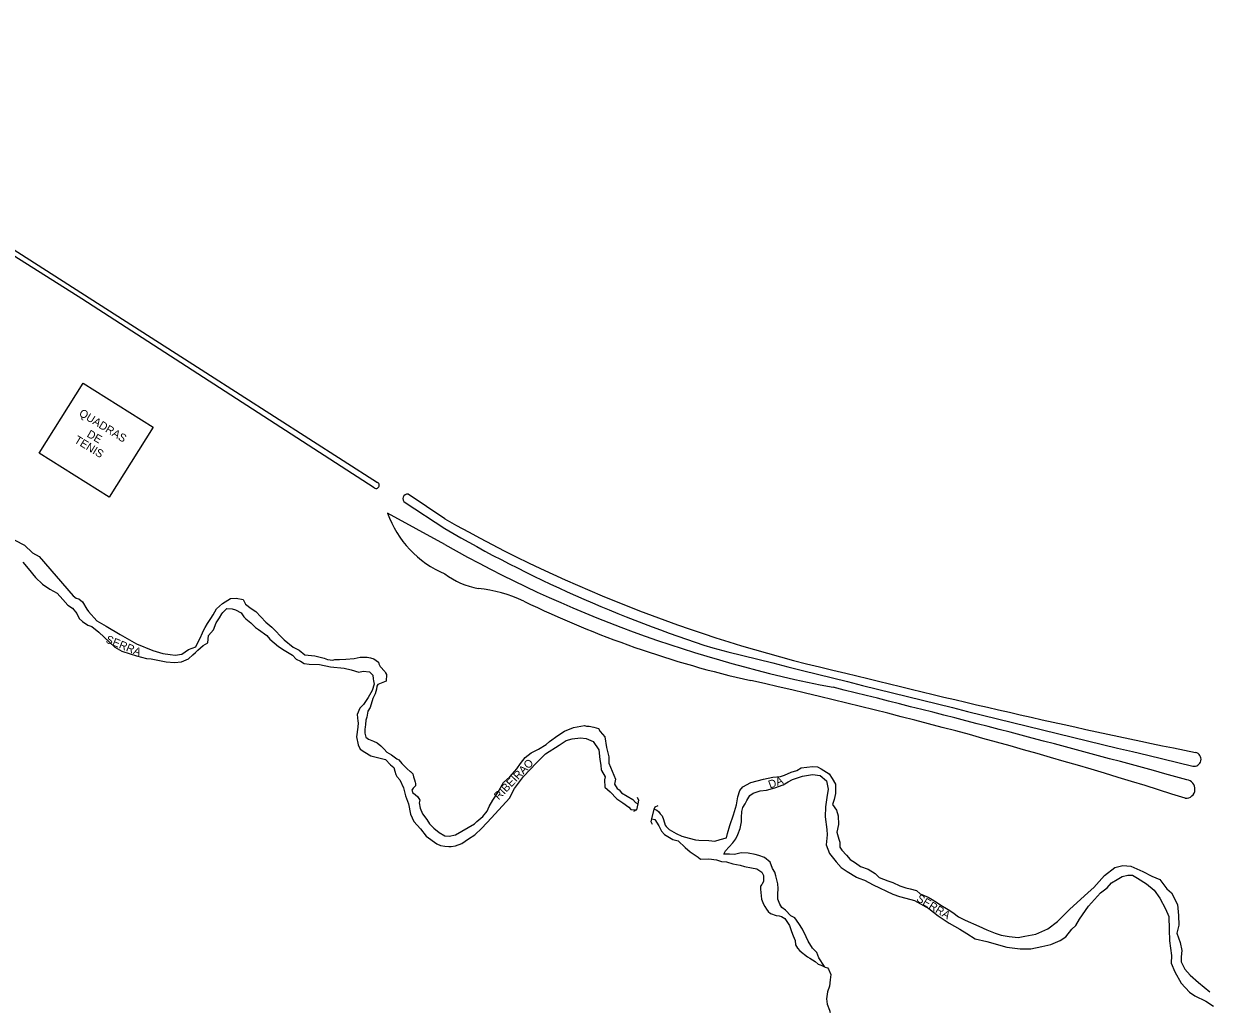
# Model space of a CAD drawing. Extents: x 325899 to 363134, y 7578590 to 7592502.
# Drawn here: x 342271 to 342864, y 7589009 to 7589502 of the extents above; entities that cross this region are included whole.
import ezdxf

# ---------------------------------------------------------------- set-up
doc = ezdxf.new("R2010")
doc.units = 0
for name, color, linetype in [('EDIFEXISTENT', 7, 'Continuous'), ('EDIFIDENTIF', 7, 'Continuous'), ('EDIFOBRAEXIS', 7, 'Continuous')]:
    doc.layers.add(name, color=color, linetype=linetype)

msp = doc.modelspace()

# ---------------------------------------------------------------- linework, layer by layer
at = {"layer": 'EDIFEXISTENT'}
for p, q in [((342278.67, 7589287.14), (342300.64, 7589322.17)), ((342300.64, 7589322.17), (342335.54, 7589300.21)), ((342335.54, 7589300.21), (342313.52, 7589265.21)), ((342313.52, 7589265.21), (342278.67, 7589287.14)), ((342577.86, 7589111.85), (342577.22, 7589108.75)), ((342577.62, 7589115.2), (342578.27, 7589113.6)), ((342578.27, 7589113.6), (342577.86, 7589111.85)), ((342577.22, 7589108.75), (342575.67, 7589107.99)), ((342584.87, 7589104.29), (342586.08, 7589109.06)), ((342586.08, 7589109.06), (342586.54, 7589110.38)), ((342586.54, 7589110.38), (342588.1, 7589110.93)), ((342584.62, 7589102.82), (342584.87, 7589104.29)), ((342585.18, 7589101.48), (342584.62, 7589102.82))]:
    msp.add_line(p, q, dxfattribs=at)
at = {"layer": 'EDIFOBRAEXIS'}
for points in [[(342446.11, 7589269.87), (342299.94, 7589364.31), (342199.85, 7589427.54), (342086.62, 7589501.91)], [(342092.03, 7589501.91), (342154.85, 7589460.08), (342361.94, 7589327.42), (342447.7, 7589272.56)], [(342481.39, 7589254.31), (342463, 7589266.71)], [(342461.57, 7589262.53), (342481.39, 7589249.43)], [(342481.39, 7589241.4), (342452.76, 7589257.13)], [(342266.44, 7589243.62), (342271.3, 7589241.16), (342275.33, 7589237.27), (342278.58, 7589235.4), (342295.64, 7589215.8), (342297.13, 7589214.57), (342298.43, 7589214.33), (342300.31, 7589212.88), (342302.43, 7589209.22), (342303.26, 7589207.91), (342307.49, 7589203.36), (342312.02, 7589200.61), (342319.06, 7589196.55), (342327.22, 7589191.77), (342335.39, 7589188.54), (342340.47, 7589186.94), (342344.01, 7589186.48), (342346.61, 7589186.18), (342349.86, 7589186.65), (342353.21, 7589188.97), (342356.91, 7589190.24), (342358.17, 7589192.82), (342359.06, 7589194.69), (342360.2, 7589197.24), (342360.95, 7589198.75), (342361.57, 7589199.98), (342362.71, 7589202.03), (342364.34, 7589204.41), (342365.59, 7589206.36), (342367.23, 7589209.27), (342370.2, 7589211.95), (342374.29, 7589214.47), (342377.13, 7589214.58), (342380.6, 7589214.01), (342381.77, 7589211.61), (342384.64, 7589209.43), (342386.92, 7589207.96), (342391.84, 7589202.7), (342394.92, 7589200.19), (342401.07, 7589193.89), (342405.64, 7589190.1), (342408.63, 7589188.69), (342411.5, 7589186.38), (342416.49, 7589185.83), (342421.16, 7589184.69), (342422.72, 7589183.92), (342425.34, 7589183.62), (342426.43, 7589183.97), (342428.79, 7589184), (342431.89, 7589184.08), (342436.03, 7589184.44), (342439.12, 7589185.19), (342442.53, 7589185.2), (342444.21, 7589184.74), (342445.95, 7589184.3), (342448.18, 7589182.6), (342448.37, 7589181.76), (342449.07, 7589180.5), (342451.46, 7589177.96), (342451.8, 7589177.33), (342452.19, 7589176.49), (342452.05, 7589173.21), (342450.38, 7589172.43), (342447.88, 7589171.46), (342447.36, 7589170.59), (342447.32, 7589169.14), (342446.64, 7589166.77), (342445.34, 7589164.46), (342444.13, 7589160), (342442.95, 7589158.13), (342442.38, 7589155.1), (342441.86, 7589153.72), (342441.71, 7589151.48), (342441.6, 7589150.19), (342441.43, 7589149.12), (342441.45, 7589147.18), (342441.91, 7589145.21), (342443.32, 7589144.18), (342445.77, 7589143.17), (342447.64, 7589142.27), (342449.44, 7589140.87), (342451.08, 7589139.11), (342452.35, 7589137.6), (342454.78, 7589136.33), (342457.34, 7589134.38), (342458.47, 7589133.81), (342459.99, 7589131.97), (342461.4, 7589130.51), (342462.66, 7589129.28), (342464, 7589128), (342464.28, 7589127.93), (342464.61, 7589127.68), (342465.41, 7589126.77), (342465.76, 7589125.36), (342466.29, 7589123.86), (342466.61, 7589122.62), (342466.69, 7589121.96), (342466.78, 7589120.84), (342466.23, 7589120.25), (342465.58, 7589119.56), (342464.93, 7589118.56), (342465.42, 7589117.24), (342466.6, 7589116.44), (342467.84, 7589115.26), (342468.87, 7589113.65), (342468.51, 7589112.37), (342469.05, 7589109.61), (342470.28, 7589106.75), (342472.37, 7589104.03), (342473.82, 7589101.83), (342475.85, 7589099.64), (342478.6, 7589097.42), (342481.39, 7589095.78)], [(342270.41, 7589232.63), (342273.04, 7589229.54), (342276.72, 7589225.01), (342280.25, 7589221.57), (342284.01, 7589219.2), (342287.57, 7589217.15), (342290.48, 7589214.04), (342292.98, 7589211.22), (342295.31, 7589209.72), (342297.4, 7589207), (342298.52, 7589204.52), (342300.32, 7589202.94), (342302.89, 7589201.09), (342304.95, 7589200.48), (342308.39, 7589197.57), (342316.41, 7589190.17), (342319.89, 7589188.1), (342324.05, 7589186.8), (342327.32, 7589185.77), (342332.21, 7589184.43), (342334.66, 7589184.23), (342337.03, 7589183.8), (342342.12, 7589182.77), (342346.19, 7589182.41), (342349.83, 7589182.76), (342353.19, 7589184.35), (342355.4, 7589186.23), (342356.78, 7589187.54), (342357.84, 7589188.65), (342360.63, 7589190.94), (342362.85, 7589192.32), (342363.32, 7589195.98), (342365.75, 7589198.73), (342367.16, 7589202.26), (342368.71, 7589204.74), (342369.9, 7589206.86), (342370.5, 7589207.51), (342372.46, 7589209.44), (342375.08, 7589209.37), (342376.69, 7589208.75), (342379.56, 7589207.28), (342381, 7589205.32), (342381.85, 7589204.39), (342384.47, 7589202.26), (342386.71, 7589200), (342388.2, 7589199.02), (342392.38, 7589195.95), (342393.92, 7589194.08), (342398.21, 7589190.55), (342401.13, 7589188.68), (342405.18, 7589186.08), (342407.06, 7589184.2), (342409.3, 7589183.16), (342411.05, 7589181.93), (342413.59, 7589181.6), (342418.73, 7589181.51), (342424.31, 7589180.31), (342431.06, 7589179.6), (342434.65, 7589178.75), (342438.4, 7589177.65), (342440.61, 7589178.16), (342443.79, 7589177.74), (342445.48, 7589176.16), (342445.61, 7589174.25), (342445.77, 7589173.29), (342446.1, 7589171.69), (342445.14, 7589168.5), (342443.07, 7589165.05), (342440.8, 7589161.39), (342438.87, 7589159.63), (342437.58, 7589156.52), (342437.95, 7589153.12), (342438.06, 7589152.33), (342437.91, 7589150.22), (342437.28, 7589145.23), (342438.14, 7589141.32), (342439.16, 7589139.15), (342441.47, 7589137.57), (342444.41, 7589135.73), (342451.83, 7589133.96), (342454.25, 7589131.24), (342455.84, 7589129.94), (342456.42, 7589128.14), (342456.93, 7589126.55), (342457.4, 7589125.54), (342458.97, 7589123.85), (342460.69, 7589119.8), (342461.7, 7589115.8), (342463.18, 7589111.75), (342464.23, 7589106.6), (342465.87, 7589103.04), (342469.22, 7589099.37), (342472, 7589095.56), (342477.37, 7589091.78), (342479.23, 7589090.9), (342481.39, 7589090.7)], [(342481.39, 7589095.78), (342483.65, 7589095.68), (342486.82, 7589096.24), (342496.18, 7589101.86), (342497.44, 7589103.01), (342500.4, 7589105.41), (342502.57, 7589108.2), (342503.61, 7589110.48), (342505.39, 7589113.65), (342507.99, 7589117.48), (342510.74, 7589122.47), (342513.95, 7589125.38), (342517.41, 7589129.23), (342519.29, 7589131.92), (342521.63, 7589134.94), (342524.61, 7589137.32), (342528.17, 7589139.14), (342532.05, 7589141.49), (342533.66, 7589142.96), (342537.83, 7589145.95), (342541.23, 7589148.2), (342545.73, 7589149.97), (342551.16, 7589150.94), (342552.23, 7589150.59), (342553.62, 7589150.61), (342555.93, 7589150.12), (342558.17, 7589149.51), (342559, 7589147.96), (342561.41, 7589145.31), (342562.28, 7589139.93), (342563.34, 7589135.31), (342563.49, 7589132.21), (342566.69, 7589124.06), (342566.16, 7589121.62), (342567.57, 7589119.46), (342568.56, 7589118.72), (342569.78, 7589117.25), (342575.33, 7589113.94), (342576.72, 7589112.54), (342577.86, 7589111.85)], [(342481.39, 7589090.7), (342483.4, 7589090.54), (342484.57, 7589090.45), (342486.73, 7589090.76), (342489.99, 7589092), (342493.22, 7589094.3), (342496.35, 7589096.38), (342499.98, 7589099.62), (342504.82, 7589104.76), (342513.67, 7589114.65), (342516.3, 7589119.51), (342520.8, 7589125.44), (342527.24, 7589132.34), (342531.79, 7589136.72), (342538.63, 7589141.22), (342542.11, 7589143.4), (342545.01, 7589144.28), (342549.17, 7589144.83), (342552.14, 7589144.47), (342555.51, 7589142.94), (342558.37, 7589138.72), (342558.92, 7589133.92), (342559.42, 7589131.15), (342559.6, 7589128.84), (342559.77, 7589128.54), (342561.54, 7589125.34), (342561.26, 7589123.76), (342561.41, 7589120.11), (342564.14, 7589117.77), (342567.46, 7589114.36), (342570.45, 7589112.22), (342573.44, 7589110.11), (342574.46, 7589109.01), (342577.22, 7589108.75)], [(342586.08, 7589109.06), (342587.07, 7589108.81), (342587.43, 7589108.61), (342588.21, 7589107.92), (342589.05, 7589106.8), (342590.04, 7589105.76), (342590.82, 7589104.03), (342591.5, 7589101.16), (342592, 7589100.5), (342593.63, 7589098.97), (342597.1, 7589096.96), (342599.97, 7589095.58), (342603.59, 7589094.64), (342606.69, 7589093.79), (342608.41, 7589093.59), (342613.36, 7589093.5), (342616.38, 7589093.19), (342619.08, 7589093.97), (342622.23, 7589094.85), (342622.69, 7589097.01), (342623.84, 7589100.94), (342625.8, 7589106.29), (342627.29, 7589111.34), (342627.9, 7589115.22), (342628.92, 7589118.39), (342630.32, 7589120.3), (342634.34, 7589122.47), (342640.72, 7589124.21), (342645.41, 7589125.11), (342649.3, 7589125.54), (342651.3, 7589126.12), (342654.53, 7589127.56), (342657.33, 7589128.54), (342659.51, 7589129.81), (342665.15, 7589130.4), (342667.66, 7589130.32), (342669.59, 7589129.23), (342673.54, 7589126.73), (342675.04, 7589124.54), (342676.68, 7589121.62), (342676.67, 7589116.93), (342676.13, 7589113.91), (342675.29, 7589111.5), (342677.21, 7589108.65), (342678.04, 7589105.88), (342678.19, 7589101.41), (342677.39, 7589097.66), (342678.32, 7589094.15), (342678.96, 7589092.6), (342678.82, 7589090.07), (342679.94, 7589088.57), (342682.19, 7589086.1), (342684.14, 7589084.04), (342686.65, 7589082.33), (342689.29, 7589080.4), (342693.02, 7589079.12), (342696.54, 7589076.93), (342698.57, 7589074.97), (342702.93, 7589073.36), (342705.42, 7589072.5), (342708.91, 7589070.79), (342711.91, 7589069.79), (342714.14, 7589069.3), (342717.26, 7589068.38), (342719.14, 7589066.86), (342723.04, 7589065.12), (342725.12, 7589064.03), (342727.25, 7589062.7), (342729.38, 7589061.05), (342733.06, 7589059.04), (342735.34, 7589057.41), (342738.23, 7589055.24), (342741.52, 7589053.69), (342748.45, 7589050.63), (342752.43, 7589048.79), (342756.56, 7589047.18), (342759.58, 7589046.19), (342763.62, 7589045.39), (342767.98, 7589045.03), (342771.41, 7589045.68), (342776.97, 7589046.69), (342782.92, 7589049.24), (342787.7, 7589052.91), (342793.8, 7589059.01), (342803.03, 7589067.42), (342805.91, 7589069.98), (342811.2, 7589075.88), (342816.44, 7589079.91), (342820.4, 7589081.02), (342824.33, 7589080.65), (342830.44, 7589078.03), (342834.83, 7589075.68), (342838.89, 7589073.9), (342842.41, 7589069.32), (342844.69, 7589067.31), (342847.77, 7589061.42), (342848.14, 7589055.98), (342848.36, 7589051.16), (342847.46, 7589047.12), (342849, 7589042.48), (342849.81, 7589038.54), (342849.52, 7589035.21), (342849.49, 7589032.78), (342851.31, 7589029.2), (342854.02, 7589026.14), (342858.23, 7589022.4), (342863.96, 7589017.82)], [(342671.27, 7589030.38), (342668.45, 7589034.85), (342667.37, 7589037.52), (342665.27, 7589039.7), (342663.04, 7589043.19), (342662.13, 7589045.27), (342660.26, 7589049.11), (342658.41, 7589051.88), (342656.46, 7589054.8), (342654.38, 7589055.8), (342651.78, 7589058.62), (342649.98, 7589059.92), (342648.94, 7589061.62), (342647.93, 7589064.13), (342647.83, 7589066.57), (342648.04, 7589069.49), (342647.84, 7589071.8), (342647.26, 7589074.42), (342646.84, 7589075.86), (342646.33, 7589077.69), (342645.24, 7589079.47), (342644.06, 7589082.62), (342641.19, 7589084.94), (342638.38, 7589085.91), (342636.53, 7589086.5), (342633.13, 7589087.09), (342629.5, 7589087.32), (342626.24, 7589086.49), (342623.68, 7589086.62), (342620.97, 7589086.6), (342621.7, 7589088.28), (342623.61, 7589090.25), (342625.39, 7589092.36), (342626.87, 7589094.36), (342627.86, 7589096.46), (342629.06, 7589099.41), (342629.73, 7589102.86), (342629.71, 7589104.99), (342629.82, 7589107.93), (342630.33, 7589109.91), (342631.6, 7589111.79), (342632.44, 7589113.51), (342633.92, 7589116), (342635.52, 7589117.06), (342639.15, 7589118.27), (342642.2, 7589118.7), (342646.34, 7589119.88), (342650.53, 7589121.3), (342653.13, 7589122.79), (342655.29, 7589123.95), (342660.21, 7589125.64), (342665.19, 7589126.49), (342669, 7589126.05), (342672.22, 7589123.31), (342673.12, 7589119.19), (342672.38, 7589114.9), (342671.66, 7589110.29), (342671.59, 7589105.23), (342672.47, 7589099.01), (342672.54, 7589096.27), (342672.12, 7589091.27), (342673.74, 7589086.93), (342677.11, 7589082.76), (342679.64, 7589079.91), (342682.58, 7589077.92), (342687.3, 7589075.1), (342688.39, 7589074.61), (342691.28, 7589073.59), (342695.49, 7589071.22), (342705.45, 7589066.61), (342708.75, 7589065.38), (342711.95, 7589064.71), (342716.24, 7589063.46), (342723.36, 7589059.44), (342728.07, 7589055.82), (342733.52, 7589052.1), (342738.9, 7589049.15), (342742.37, 7589046.98), (342746.58, 7589044.23), (342752.32, 7589042.9), (342762.41, 7589040.11), (342769.09, 7589039.37), (342774.44, 7589039.33), (342779.85, 7589040.54), (342784.4, 7589041.52), (342789, 7589043.49), (342791.89, 7589045.23), (342794.87, 7589049.11), (342796.96, 7589051.01), (342798.69, 7589054.18), (342803.22, 7589060.69), (342809.18, 7589067.33), (342812.53, 7589069.76), (342814.75, 7589072.25), (342817.49, 7589073.97), (342820.08, 7589075.41), (342822.95, 7589076.14), (342825.24, 7589076.11), (342827.77, 7589074.61), (342832.23, 7589071.75), (342836.11, 7589068.6), (342838.95, 7589064.58), (342841.75, 7589059.27), (342843.34, 7589055.41), (342843.48, 7589049.01), (342843.78, 7589043.35), (342844.73, 7589035.91), (342844.49, 7589032.13), (342846.43, 7589027.71), (342849.6, 7589022.12), (342853.65, 7589017.69), (342856.36, 7589015.73), (342861.89, 7589013.16), (342865.8, 7589010.64)], [(342584.87, 7589104.29), (342586.33, 7589103.91), (342588.4, 7589100.78), (342589.74, 7589098.17), (342591.18, 7589096.41), (342595.37, 7589093.99), (342598.03, 7589093.33), (342601.65, 7589089.94), (342604.11, 7589087.76), (342608.09, 7589085.06), (342609.31, 7589084.09), (342613.35, 7589084.28), (342617.23, 7589083.72), (342619.66, 7589082.88), (342622.23, 7589082.72), (342625.47, 7589081.8), (342629.05, 7589081.21), (342631.16, 7589080.42), (342634.66, 7589079.82), (342637.42, 7589079.23), (342639.83, 7589077.58), (342640.77, 7589075.95), (342640.76, 7589072.98), (342640.02, 7589071.79), (342639.85, 7589071.44), (342639.26, 7589070.63), (342639.21, 7589069.13), (342639.46, 7589067.5), (342639.68, 7589064.2), (342640.69, 7589061.71), (342641.42, 7589060.42), (342642.26, 7589059.15), (342643.02, 7589057.9), (342644.28, 7589056.88), (342647.07, 7589055.99), (342648.55, 7589055.83), (342649.81, 7589055.4), (342651.46, 7589054.51), (342653.66, 7589050.92), (342654.67, 7589048.03), (342655.56, 7589045.84), (342656.59, 7589043.38), (342656.69, 7589041.37), (342657.68, 7589039.67), (342658.87, 7589038.3), (342662.74, 7589035.22), (342663.83, 7589034.63), (342666.5, 7589032.9), (342668.14, 7589031.65), (342669.64, 7589031.17), (342671.64, 7589030.2), (342672.73, 7589029.76), (342673.19, 7589029.15), (342674.4, 7589026.44), (342674.07, 7589023.8), (342673.78, 7589020.67), (342672.79, 7589017.81), (342672.17, 7589014.26), (342672.6, 7589011.56), (342673.68, 7589008.69), (342674.06, 7589007.4)]]:
    msp.add_lwpolyline(points, dxfattribs=at)
for centre, radius, start, end in [((342447.07, 7589271.11), 1.58, 232.06916, 66.55855), ((342462.73, 7589264.47), 2.26, 83.18585, 239.21532), ((342501.49, 7589274.47), 51.72, 199.58111, 247.12824), ((342839.46, 7589886.25), 726.33, 240.46358, 257.47646), ((342824.73, 7589840.11), 683.22, 239.83195, 252.15443), ((342797.36, 7589801.47), 643.05, 240.56974, 259.07626), ((342505.65, 7589259.32), 40.56, 233.26345, 259.24371), ((342490.86, 7589148.9), 70.94, 64.96186, 84.15476), ((342748.18, 7589680.87), 520.01, 244.08029, 257.35982), ((348659.11, 7613195.07), 24754.42, 255.868502, 256.440544), ((343616.01, 7592884.42), 3823.07, 255.85844, 258.54481), ((342074.69, 7586679.5), 2555.99, 72.30438, 77.35123), ((341073.19, 7582679.16), 6685.76, 74.567206, 76.13345), ((342855.97, 7589134.07), 3.51, 259.41992, 77.40014), ((342851.82, 7589119.22), 4.66, 267.41209, 83.91472)]:
    msp.add_arc(centre, radius, start, end, dxfattribs=at)

# ---------------------------------------------------------------- texts
at = {"layer": 'EDIFIDENTIF'}
for s, rotation, p in [('QUADRAS', 328.54125, (342298.15, 7589306.14)), ('TENIS', 328.73437, (342295.81, 7589292.74)), ('DE', 329.95487, (342302.11, 7589295.59)), ('SERRA', 337.76452, (342311.53, 7589192.55)), ('RIBEIRAO', 46.24564, (342508.42, 7589113.47)), ('DA', 20.39284, (342644.03, 7589119.4)), ('SERRA', 328.78224, (342716.87, 7589063.44))]:
    msp.add_text(s, height=4, rotation=rotation, dxfattribs=at).set_placement(p)

doc.saveas('drawing.dxf')
